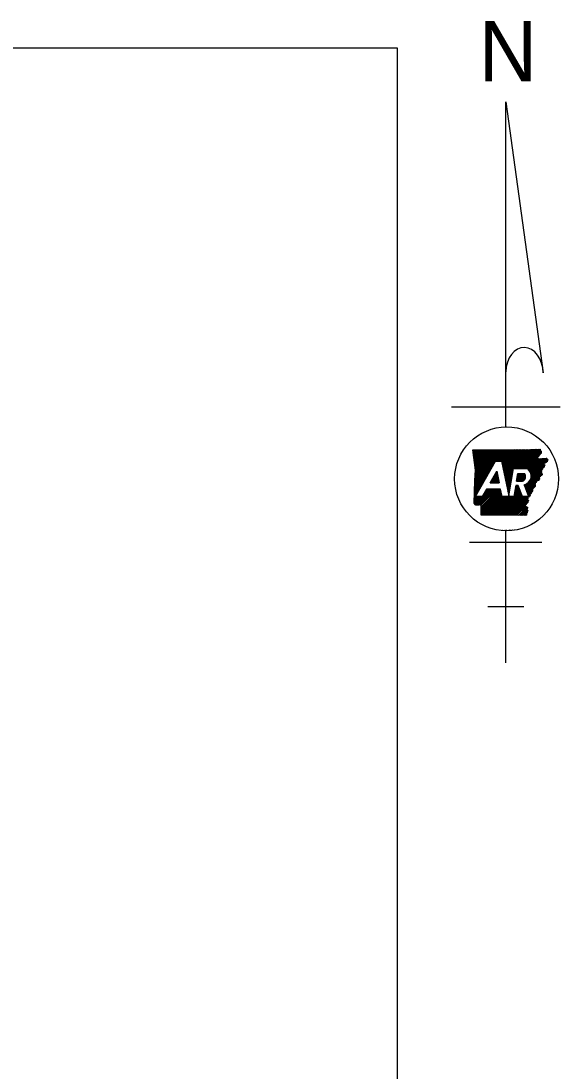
# Model space of a CAD drawing. Extents: x -984 to 3998, y 83 to 2143.
# Drawn here: x 751 to 1030, y 1535 to 2078 of the extents above; entities that cross this region are included whole.
import ezdxf

# ---------------------------------------------------------------- set-up
doc = ezdxf.new("R2010")
doc.units = 0
doc.layers.add('Level 47', color=7, linetype='Continuous')
doc.layers.add('Level 57', color=7, linetype='Continuous')

msp = doc.modelspace()

# ---------------------------------------------------------------- linework, layer by layer
at = {"layer": 'Level 47'}
for p, q in [((1002.31, 2036.19), (1021.71, 1895.95)), ((1002.31, 1868.02), (1002.31, 2036.19)), ((974.22, 1878.42), (1030.38, 1878.42)), ((985.27, 1855.97), (985.5, 1856.2)), ((985.35, 1855.31), (986.24, 1856.2)), ((985.43, 1854.65), (986.99, 1856.2)), ((985.52, 1853.99), (987.73, 1856.2)), ((985.6, 1853.33), (988.47, 1856.2)), ((985.68, 1852.67), (989.22, 1856.2)), ((985.76, 1852.01), (989.96, 1856.2)), ((985.85, 1851.35), (990.7, 1856.2)), ((985.93, 1850.68), (991.44, 1856.2)), ((986.01, 1850.02), (992.19, 1856.2)), ((986.09, 1849.36), (992.93, 1856.2)), ((986.18, 1848.7), (993.67, 1856.2)), ((986.26, 1848.04), (994.42, 1856.2)), ((986.34, 1847.38), (995.16, 1856.2)), ((986.37, 1839.97), (1002.61, 1856.21)), ((986.39, 1840.74), (1001.86, 1856.21)), ((986.42, 1841.51), (1001.12, 1856.21)), ((986.42, 1846.72), (995.9, 1856.2)), ((986.44, 1842.28), (1000.37, 1856.21)), ((986.47, 1843.05), (999.63, 1856.21)), ((986.49, 1843.82), (998.88, 1856.21)), ((986.51, 1846.06), (996.65, 1856.2)), ((986.52, 1844.58), (998.14, 1856.2)), ((986.54, 1845.35), (997.39, 1856.2)), ((997.4, 1850.27), (1003.35, 1856.21)), ((998.15, 1850.27), (1004.1, 1856.22)), ((998.89, 1850.27), (1004.85, 1856.22)), ((999.63, 1850.27), (1005.6, 1856.23)), ((1000.1, 1849.99), (1006.36, 1856.25)), ((1000.23, 1849.37), (1007.11, 1856.26)), ((1000.36, 1848.76), (1007.87, 1856.27)), ((1000.49, 1848.15), (1008.62, 1856.28)), ((1000.62, 1847.54), (1009.38, 1856.29)), ((1000.75, 1846.92), (1010.13, 1856.3)), ((1000.88, 1846.31), (1010.89, 1856.32)), ((1001.01, 1845.7), (1011.64, 1856.33)), ((1001.15, 1845.09), (1012.4, 1856.34)), ((1001.28, 1844.48), (1013.15, 1856.35)), ((1001.41, 1843.86), (1013.91, 1856.36)), ((1001.54, 1843.25), (1014.66, 1856.38)), ((1001.67, 1842.64), (1015.42, 1856.39)), ((1001.8, 1842.03), (1016.18, 1856.41)), ((1006.96, 1846.45), (1016.94, 1856.42)), ((1007.71, 1846.45), (1017.7, 1856.44)), ((1008.45, 1846.45), (1018.46, 1856.46)), ((1009.19, 1846.45), (1019.23, 1856.48)), ((1009.94, 1846.45), (1019.99, 1856.5)), ((1010.68, 1846.45), (1020.15, 1855.92)), ((1011.42, 1846.45), (1020.51, 1855.53)), ((1012.17, 1846.45), (1020.61, 1854.89)), ((986.31, 1838.43), (995.4, 1847.52)), ((986.34, 1839.2), (996.37, 1849.23)), ((986.59, 1831.95), (996.96, 1850.27)), ((996.96, 1850.27), (1000.04, 1850.27)), ((1012.91, 1846.45), (1018.91, 1852.45)), ((1013.59, 1846.38), (1018.76, 1851.56)), ((1013.99, 1846.04), (1019.55, 1851.6)), ((1014.35, 1845.66), (1020.33, 1851.64)), ((1014.68, 1845.24), (1021.11, 1851.68)), ((1014.95, 1844.77), (1021.9, 1851.72)), ((1015.18, 1844.25), (1022.68, 1851.76)), ((1015.3, 1841.4), (1022.05, 1848.15)), ((1015.35, 1843.68), (1023.39, 1851.72)), ((1015.45, 1843.04), (1023.73, 1851.32)), ((1015.46, 1842.3), (1021.96, 1848.81)), ((1021.21, 1846.57), (1022.13, 1847.49)), ((1023.41, 1850.25), (1024.08, 1850.93)), ((986.24, 1836.13), (992.49, 1842.38)), ((986.26, 1836.9), (993.46, 1844.09)), ((986.29, 1837.66), (994.43, 1845.81)), ((994.21, 1839.14), (997.61, 1845.13)), ((994.25, 1839.14), (998.07, 1842.96)), ((994.99, 1839.14), (998.2, 1842.35)), ((995.14, 1840.77), (997.94, 1843.57)), ((996.11, 1842.49), (997.81, 1844.19)), ((997.08, 1844.2), (997.68, 1844.8)), ((1001.93, 1841.41), (1006.15, 1845.63)), ((1002.06, 1840.8), (1005.99, 1844.73)), ((1002.19, 1840.19), (1005.84, 1843.83)), ((1002.32, 1839.58), (1005.68, 1842.93)), ((1002.46, 1838.96), (1005.52, 1842.03)), ((1006.29, 1846.45), (1013.49, 1846.45)), ((1007.86, 1839.95), (1011.77, 1843.86)), ((1008.01, 1840.85), (1011.03, 1843.86)), ((1008.17, 1841.75), (1010.28, 1843.86)), ((1008.32, 1842.65), (1009.54, 1843.86)), ((1008.48, 1843.55), (1008.8, 1843.86)), ((1008.54, 1843.86), (1011.92, 1843.86)), ((1008.6, 1839.95), (1012.18, 1843.53)), ((1009.35, 1839.95), (1012.43, 1843.04)), ((1010.09, 1839.95), (1012.57, 1842.43)), ((1012.23, 1836.85), (1020.47, 1845.09)), ((1012.43, 1836.3), (1020.61, 1844.48)), ((1012.63, 1835.76), (1020.75, 1843.88)), ((1012.83, 1835.22), (1020.89, 1843.27)), ((1014.65, 1840.01), (1020.33, 1845.69)), ((986.16, 1833.82), (989.58, 1837.24)), ((986.19, 1834.59), (990.55, 1838.95)), ((986.21, 1835.36), (991.52, 1840.66)), ((994.21, 1839.14), (998.89, 1839.14)), ((995.74, 1839.14), (998.33, 1841.74)), ((996.48, 1839.14), (998.46, 1841.12)), ((997.22, 1839.14), (998.59, 1840.51)), ((997.97, 1839.14), (998.73, 1839.9)), ((998.71, 1839.14), (998.86, 1839.29)), ((1002.59, 1838.35), (1005.36, 1841.13)), ((1002.72, 1837.74), (1005.21, 1840.23)), ((1002.85, 1837.13), (1005.05, 1839.33)), ((1002.98, 1836.52), (1004.89, 1838.43)), ((1003.11, 1835.9), (1004.74, 1837.53)), ((1003.24, 1835.29), (1004.58, 1836.63)), ((1006.9, 1834.49), (1009.12, 1836.71)), ((1007.06, 1835.39), (1008.92, 1837.25)), ((1007.22, 1836.29), (1008.7, 1837.78)), ((1007.37, 1837.19), (1007.96, 1837.78)), ((1008.72, 1837.78), (1007.48, 1837.78)), ((1007.85, 1839.95), (1010.94, 1839.95)), ((1010.88, 1831.95), (1008.72, 1837.78)), ((1010.83, 1839.95), (1012.51, 1841.63)), ((1011.77, 1838.09), (1014.04, 1831.95)), ((1011.83, 1837.93), (1012.06, 1838.16)), ((1012.03, 1837.39), (1013.44, 1838.8)), ((1013.03, 1834.68), (1017.49, 1839.13)), ((1013.23, 1834.13), (1017.41, 1838.31)), ((1013.43, 1833.59), (1017.32, 1837.48)), ((1018.35, 1839.99), (1019.39, 1841.03)), ((985.99, 1828.45), (989.5, 1831.95)), ((986.01, 1829.21), (988.75, 1831.95)), ((986.03, 1829.98), (988.01, 1831.95)), ((986.06, 1830.75), (987.27, 1831.95)), ((986.08, 1831.51), (986.67, 1832.1)), ((986.11, 1832.28), (987.64, 1833.81)), ((986.14, 1833.05), (988.61, 1835.52)), ((986.27, 1827.98), (994.08, 1835.8)), ((990.14, 1831.95), (986.59, 1831.95)), ((986.71, 1827.68), (994.83, 1835.8)), ((987.25, 1827.47), (995.57, 1835.8)), ((988.13, 1827.61), (996.31, 1835.8)), ((988.88, 1827.62), (997.06, 1835.8)), ((989.47, 1827.46), (997.8, 1835.8)), ((989.49, 1826), (999.29, 1835.8)), ((989.49, 1826.74), (998.54, 1835.8)), ((989.5, 1825.26), (999.68, 1835.44)), ((989.5, 1824.52), (999.81, 1834.83)), ((989.5, 1823.78), (999.94, 1834.22)), ((989.5, 1823.04), (1000.07, 1833.61)), ((989.51, 1822.31), (1000.2, 1833)), ((992.32, 1835.8), (990.14, 1831.95)), ((990.26, 1822.31), (1000.33, 1832.38)), ((990.99, 1833.44), (993.34, 1835.8)), ((991, 1822.3), (1000.65, 1831.95)), ((991.74, 1822.3), (1001.39, 1831.95)), ((991.96, 1835.16), (992.6, 1835.8)), ((999.6, 1835.8), (992.32, 1835.8)), ((992.48, 1822.3), (1002.13, 1831.95)), ((993.22, 1822.3), (1002.88, 1831.95)), ((993.97, 1822.3), (1003.62, 1831.95)), ((994.71, 1822.3), (1004.36, 1831.95)), ((995.45, 1822.3), (1005.11, 1831.95)), ((996.19, 1822.3), (1005.85, 1831.95)), ((996.94, 1822.29), (1009.72, 1835.08)), ((997.68, 1822.29), (1009.92, 1834.54)), ((998.42, 1822.29), (1010.12, 1833.99)), ((999.16, 1822.29), (1010.32, 1833.45)), ((999.9, 1822.29), (1010.52, 1832.91)), ((1006.46, 1831.95), (1000.43, 1831.95)), ((1000.65, 1822.29), (1010.72, 1832.37)), ((1001.39, 1822.29), (1011.05, 1831.95)), ((1002.13, 1822.29), (1011.8, 1831.95)), ((1002.87, 1822.28), (1012.54, 1831.95)), ((1003.37, 1834.68), (1004.42, 1835.73)), ((1003.5, 1834.07), (1004.27, 1834.83)), ((1003.61, 1822.28), (1013.28, 1831.95)), ((1003.63, 1833.45), (1004.11, 1833.93)), ((1003.77, 1832.84), (1003.95, 1833.03)), ((1004.36, 1822.28), (1013.53, 1831.46)), ((1006.59, 1832.69), (1009.52, 1835.62)), ((1006.75, 1833.59), (1009.32, 1836.16)), ((1014.04, 1831.95), (1010.88, 1831.95)), ((1013.63, 1833.05), (1015.91, 1835.33)), ((1013.83, 1832.5), (1015.6, 1834.26)), ((1005.1, 1822.28), (1013.57, 1830.75)), ((1005.84, 1822.28), (1013.6, 1830.04)), ((1006.58, 1822.28), (1013.63, 1829.33)), ((1007.32, 1822.28), (1012.41, 1827.36)), ((1008.07, 1822.28), (1012.64, 1826.85)), ((1008.81, 1822.27), (1012.87, 1826.34)), ((1009.55, 1822.27), (1013.1, 1825.82)), ((1010.29, 1822.27), (1013.33, 1825.31)), ((1011.04, 1822.27), (1013.52, 1824.76)), ((1011.78, 1822.27), (1013.19, 1823.68)), ((1012.52, 1822.27), (1012.85, 1822.6)), ((1002.31, 1745.97), (1002.31, 1814.22)), ((983.59, 1808.42), (1021.03, 1808.42)), ((992.94, 1775.17), (1011.67, 1775.17))]:
    msp.add_line(p, q, dxfattribs=at)
for points in [[(985.24, 1856.2), (995.49, 1856.2), (1004.5, 1856.22), (1015.11, 1856.38), (1020.03, 1856.5)], [(985.24, 1856.2), (995.5, 1856.2), (1004.5, 1856.22), (1015.11, 1856.38), (1020.03, 1856.5)], [(986.37, 1840.26), (986.55, 1845.66), (985.24, 1856.2)], [(985.98, 1828.46), (986.55, 1845.66), (985.24, 1856.2)], [(1000.04, 1850.27), (1003.85, 1832.44), (1006.29, 1846.45)], [(1023.26, 1851.78), (1024.14, 1850.86), (1021.93, 1849.04), (1022.17, 1847.2), (1020.27, 1845.95), (1020.92, 1843.13), (1019.46, 1841.79), (1019.33, 1840.34), (1017.55, 1839.7), (1017.27, 1836.97), (1016, 1835.6), (1015.38, 1833.54), (1013.52, 1831.83), (1013.66, 1828.83), (1012.39, 1827.41), (1013.54, 1824.83), (1012.75, 1822.27)], [(1018.51, 1851.55), (1023.32, 1851.79)], [(1018.51, 1851.54), (1023.33, 1851.79)], [(997.61, 1845.13), (998.89, 1839.14)], [(1007.85, 1839.95), (1008.54, 1843.86)], [(985.99, 1828.46), (986.37, 1840.26)], [(1007.48, 1837.78), (1006.46, 1831.95)], [(1000.43, 1831.95), (999.6, 1835.8)], [(1012.75, 1822.27), (989.5, 1822.31), (989.49, 1827.44)], [(1012.75, 1822.27), (989.5, 1822.31), (989.49, 1827.44)]]:
    msp.add_lwpolyline(points, dxfattribs=at)
for centre, major_axis, ratio, start_param, end_param in [((1012, 1895.65), (-0.41, 13.48), 0.719778, 4.712385, 7.768526), ((1010.2, 1842.21), (-2.38, 0), 0.999987, 1.887169, 3.90762), ((1010.82, 1842.64), (-4.65, 0), 0.999987, 1.777838, 4.099264)]:
    msp.add_ellipse(centre, major_axis=major_axis, ratio=ratio, start_param=start_param, end_param=end_param, dxfattribs=at)
msp.add_ellipse((1002.74, 1841.12), major_axis=(26.9, 0), ratio=0.999976, dxfattribs=at)
for points in [[(1020.03, 1856.5), (1020.07, 1856.22), (1020.15, 1856.07), (1020.16, 1855.8), (1020.27, 1855.69), (1020.46, 1855.58), (1020.62, 1855.39), (1020.66, 1855.18), (1020.61, 1854.96), (1020.6, 1854.7), (1020.57, 1854.49), (1020.53, 1854.3), (1020.38, 1854.14), (1020.24, 1854.02), (1020.1, 1853.89), (1020.01, 1853.75), (1019.85, 1853.6), (1019.68, 1853.44), (1019.54, 1853.3), (1019.41, 1853.12), (1019.35, 1852.93), (1019.2, 1852.79), (1019.09, 1852.66), (1018.94, 1852.49), (1018.86, 1852.32), (1018.72, 1852.12), (1018.68, 1851.93), (1018.59, 1851.78), (1018.58, 1851.75)], [(1020.03, 1856.5), (1020.07, 1856.22), (1020.15, 1856.07), (1020.17, 1855.81), (1020.27, 1855.69), (1020.46, 1855.58), (1020.62, 1855.39), (1020.66, 1855.18), (1020.61, 1854.96), (1020.6, 1854.71), (1020.57, 1854.49), (1020.54, 1854.3), (1020.38, 1854.14), (1020.24, 1854.02), (1020.1, 1853.89), (1020.01, 1853.75), (1019.84, 1853.6), (1019.68, 1853.44), (1019.55, 1853.3), (1019.41, 1853.12), (1019.35, 1852.93), (1019.2, 1852.79), (1019.09, 1852.66), (1018.94, 1852.49), (1018.86, 1852.32), (1018.71, 1852.12), (1018.68, 1851.93), (1018.59, 1851.78), (1018.58, 1851.75)], [(1023.26, 1851.79), (1023.32, 1851.79), (1023.54, 1851.56), (1023.63, 1851.37), (1023.78, 1851.27), (1023.94, 1851.21), (1024.06, 1851.06), (1024.14, 1850.9), (1024.09, 1850.76), (1023.91, 1850.75), (1023.72, 1850.72), (1023.53, 1850.73), (1023.37, 1850.59), (1023.52, 1850.43), (1023.7, 1850.27), (1023.75, 1850.1), (1023.65, 1849.93), (1023.44, 1849.84), (1023.25, 1849.76), (1023.07, 1849.62), (1022.99, 1849.47), (1022.79, 1849.41), (1022.59, 1849.35), (1022.41, 1849.33), (1022.21, 1849.29), (1022.01, 1849.19), (1021.93, 1849.03), (1021.96, 1848.8), (1021.95, 1848.55), (1022.16, 1848.47), (1022.34, 1848.46), (1022.52, 1848.37), (1022.5, 1848.23), (1022.37, 1848.05), (1022.21, 1847.91), (1022.05, 1847.84), (1021.9, 1847.7), (1021.96, 1847.57), (1022.09, 1847.49), (1022.18, 1847.34), (1022.17, 1847.21), (1022.02, 1847.11), (1021.85, 1847.15), (1021.73, 1847.31), (1021.59, 1847.36), (1021.47, 1847.41), (1021.33, 1847.33), (1021.33, 1847.15), (1021.28, 1846.95), (1021.33, 1846.81), (1021.38, 1846.6), (1021.38, 1846.45), (1021.33, 1846.23), (1021.22, 1846.01), (1021.1, 1845.94), (1021.04, 1846.18), (1021.02, 1846.38), (1020.94, 1846.5), (1020.84, 1846.5), (1020.7, 1846.41), (1020.56, 1846.26), (1020.38, 1846.1), (1020.27, 1845.94), (1020.33, 1845.75), (1020.46, 1845.7), (1020.57, 1845.73), (1020.63, 1845.86), (1020.73, 1845.88), (1020.84, 1845.68)], [(1020.84, 1845.68), (1020.87, 1845.5), (1020.76, 1845.31), (1020.72, 1845.11), (1020.73, 1844.91), (1020.53, 1844.8), (1020.36, 1844.67), (1020.46, 1844.52), (1020.65, 1844.38), (1020.84, 1844.28), (1020.96, 1844.17), (1020.99, 1843.91), (1021.02, 1843.74), (1021.09, 1843.51), (1021.11, 1843.36), (1021, 1843.17), (1020.87, 1843.13), (1020.72, 1843.17), (1020.56, 1843.18), (1020.43, 1843.06), (1020.33, 1842.88), (1020.24, 1842.7), (1020.16, 1842.55), (1020.09, 1842.39), (1019.96, 1842.19), (1019.79, 1842.16), (1019.58, 1842.11), (1019.46, 1841.97), (1019.48, 1841.74), (1019.6, 1841.58), (1019.68, 1841.39), (1019.75, 1841.21), (1019.72, 1841), (1019.63, 1840.84), (1019.52, 1840.74), (1019.46, 1840.54), (1019.38, 1840.39), (1019.3, 1840.33), (1019.15, 1840.35), (1018.99, 1840.38), (1018.85, 1840.37), (1018.72, 1840.3), (1018.58, 1840.34), (1018.44, 1840.5), (1018.33, 1840.61), (1018.2, 1840.65), (1018.07, 1840.58), (1018.05, 1840.37), (1018.11, 1840.16), (1018.16, 1839.87), (1018.11, 1839.69), (1018.09, 1839.4)], [(1018.09, 1839.4), (1017.87, 1839.23), (1017.76, 1839.05), (1017.2, 1839.1), (1017.22, 1838.91), (1017.02, 1838.8), (1016.84, 1838.67), (1016.94, 1838.52), (1017.13, 1838.38), (1017.32, 1838.27), (1017.44, 1838.17), (1017.47, 1837.9), (1017.51, 1837.74), (1017.57, 1837.51), (1017.59, 1837.35), (1017.48, 1837.17), (1017.34, 1837.13), (1017.21, 1837.17), (1017.04, 1837.18), (1016.91, 1837.06), (1016.81, 1836.88), (1016.72, 1836.7), (1016.65, 1836.55), (1016.57, 1836.38), (1016.44, 1836.19), (1016.27, 1836.16), (1016.07, 1836.11), (1015.94, 1835.97), (1015.96, 1835.74), (1016.08, 1835.58), (1016.17, 1835.38), (1016.23, 1835.21), (1016.2, 1835), (1016.11, 1834.83), (1016, 1834.74), (1015.94, 1834.54), (1015.86, 1834.38), (1015.79, 1834.34), (1015.64, 1834.35), (1015.47, 1834.38), (1015.33, 1834.37), (1015.2, 1834.3), (1015.06, 1834.34), (1014.92, 1834.49), (1014.81, 1834.61), (1014.68, 1834.65), (1014.55, 1834.58), (1014.53, 1834.37), (1014.59, 1834.16), (1014.65, 1833.87), (1014.59, 1833.69), (1014.57, 1833.39)], [(1014.57, 1833.39), (1014.55, 1833.39), (1014.44, 1833.24), (1014.5, 1833.02), (1014.75, 1832.93), (1014.86, 1832.72), (1014.87, 1832.53), (1014.79, 1832.27), (1014.67, 1832.14), (1014.45, 1832.09), (1014.28, 1832.06), (1014.26, 1831.77), (1014.18, 1831.62), (1014.05, 1831.58), (1013.86, 1831.67), (1013.74, 1831.72), (1013.6, 1831.78), (1013.43, 1831.89), (1013.29, 1831.87), (1013.33, 1831.59), (1013.34, 1831.58), (1013.5, 1831.37), (1013.64, 1831.2), (1013.71, 1831.01)], [(1014.57, 1833.39), (1014.55, 1833.39), (1014.44, 1833.24), (1014.5, 1833.02), (1014.75, 1832.93), (1014.86, 1832.72), (1014.87, 1832.53), (1014.79, 1832.27), (1014.67, 1832.14), (1014.45, 1832.09), (1014.28, 1832.06), (1014.26, 1831.77), (1014.18, 1831.62), (1014.05, 1831.58), (1013.86, 1831.67), (1013.74, 1831.72), (1013.6, 1831.78), (1013.43, 1831.89), (1013.29, 1831.87), (1013.33, 1831.59), (1013.34, 1831.58), (1013.5, 1831.37), (1013.64, 1831.2), (1013.71, 1831.01)], [(989.49, 1827.44), (989.52, 1827.42), (989.4, 1827.51), (989.23, 1827.59), (989.05, 1827.6), (988.81, 1827.63), (988.62, 1827.65), (988.41, 1827.79), (988.2, 1827.65), (987.96, 1827.55), (987.82, 1827.66), (987.63, 1827.58), (987.51, 1827.62), (987.28, 1827.47), (987.07, 1827.53), (986.92, 1827.48), (986.73, 1827.49), (986.69, 1827.7), (986.51, 1827.74), (986.35, 1827.82), (986.24, 1828.05), (986.17, 1828.22), (985.98, 1828.46)], [(989.49, 1827.44), (989.52, 1827.43), (989.4, 1827.51), (989.23, 1827.59), (989.04, 1827.6), (988.81, 1827.63), (988.61, 1827.65), (988.41, 1827.79), (988.2, 1827.65), (987.96, 1827.54), (987.82, 1827.66), (987.63, 1827.58), (987.5, 1827.62), (987.28, 1827.47), (987.07, 1827.53), (986.92, 1827.48), (986.73, 1827.49), (986.69, 1827.7), (986.51, 1827.73), (986.35, 1827.82), (986.24, 1828.04), (986.17, 1828.22), (985.99, 1828.46)], [(1013.71, 1831.01), (1013.65, 1830.86), (1013.58, 1830.61), (1013.6, 1830.39), (1013.7, 1830.21), (1013.85, 1830.11), (1014.02, 1829.96), (1014, 1829.74), (1013.91, 1829.66), (1013.68, 1829.71), (1013.51, 1829.79), (1013.37, 1829.75), (1013.17, 1829.65), (1013.03, 1829.63), (1013.03, 1829.33), (1013.23, 1829.11), (1013.4, 1829.11), (1013.6, 1829.09), (1013.67, 1828.86), (1013.55, 1828.67), (1013.36, 1828.57), (1013.12, 1828.69), (1012.95, 1828.81), (1012.78, 1828.92), (1012.56, 1828.98), (1012.44, 1828.95), (1012.38, 1828.69), (1012.49, 1828.45), (1012.65, 1828.28), (1012.8, 1828.07), (1012.78, 1827.9), (1012.66, 1827.86), (1012.46, 1827.82), (1012.34, 1827.76), (1012.31, 1827.7), (1012.37, 1827.49), (1012.43, 1827.26), (1012.43, 1827.07), (1012.36, 1826.91), (1012.25, 1826.66), (1012.26, 1826.5), (1012.34, 1826.42), (1012.44, 1826.44), (1012.56, 1826.53), (1012.65, 1826.63), (1012.72, 1826.76), (1012.85, 1826.87), (1013.01, 1826.77), (1013.05, 1826.57), (1012.96, 1826.41), (1012.82, 1826.33), (1012.66, 1826.26), (1012.54, 1826.13), (1012.57, 1825.96), (1012.66, 1825.87), (1012.9, 1825.92), (1013.06, 1825.99), (1013.15, 1826.07), (1013.25, 1826.18), (1013.31, 1826.29), (1013.39, 1826.41), (1013.54, 1826.44), (1013.61, 1826.34), (1013.58, 1826.13), (1013.5, 1825.92), (1013.37, 1825.75), (1013.24, 1825.63), (1013.08, 1825.37), (1013.11, 1825.13), (1013.17, 1824.93), (1013.26, 1824.78), (1013.41, 1824.81), (1013.58, 1824.83), (1013.68, 1824.75), (1013.67, 1824.57), (1013.55, 1824.4), (1013.43, 1824.23), (1013.36, 1824.01), (1013.39, 1823.85), (1013.39, 1823.71), (1013.34, 1823.54), (1013.25, 1823.45), (1013.01, 1823.46), (1012.77, 1823.48), (1012.63, 1823.41), (1012.66, 1823.2), (1012.8, 1823.04), (1012.9, 1822.95), (1013.05, 1822.78), (1013.11, 1822.63), (1013.1, 1822.5), (1013, 1822.39), (1012.75, 1822.27)], [(1013.71, 1831.01), (1013.65, 1830.86), (1013.58, 1830.61), (1013.6, 1830.39), (1013.7, 1830.21), (1013.85, 1830.11), (1014.02, 1829.96), (1014, 1829.74), (1013.91, 1829.66), (1013.68, 1829.71), (1013.51, 1829.79), (1013.37, 1829.75), (1013.17, 1829.65), (1013.03, 1829.63), (1013.03, 1829.33), (1013.23, 1829.11), (1013.4, 1829.11), (1013.6, 1829.09), (1013.67, 1828.86), (1013.55, 1828.67), (1013.36, 1828.57), (1013.12, 1828.69), (1012.95, 1828.81), (1012.78, 1828.92), (1012.56, 1828.98), (1012.44, 1828.95), (1012.38, 1828.69), (1012.49, 1828.45), (1012.65, 1828.28), (1012.8, 1828.07), (1012.78, 1827.9), (1012.66, 1827.86), (1012.46, 1827.82), (1012.34, 1827.76), (1012.31, 1827.7), (1012.37, 1827.49), (1012.43, 1827.26), (1012.43, 1827.07), (1012.36, 1826.91), (1012.25, 1826.66), (1012.26, 1826.5), (1012.34, 1826.42), (1012.44, 1826.44), (1012.56, 1826.53), (1012.65, 1826.63), (1012.72, 1826.76), (1012.85, 1826.87), (1013.01, 1826.77), (1013.05, 1826.57), (1012.96, 1826.41), (1012.82, 1826.33), (1012.66, 1826.26), (1012.54, 1826.13), (1012.57, 1825.96), (1012.66, 1825.87), (1012.9, 1825.92), (1013.06, 1825.99), (1013.15, 1826.07), (1013.25, 1826.18), (1013.31, 1826.29), (1013.39, 1826.41), (1013.54, 1826.44), (1013.61, 1826.34), (1013.58, 1826.13), (1013.5, 1825.92), (1013.37, 1825.75), (1013.24, 1825.63), (1013.08, 1825.37), (1013.11, 1825.13), (1013.17, 1824.93), (1013.26, 1824.78), (1013.41, 1824.81), (1013.58, 1824.83), (1013.68, 1824.75), (1013.67, 1824.57), (1013.55, 1824.4), (1013.43, 1824.23), (1013.36, 1824.01), (1013.39, 1823.85), (1013.39, 1823.71), (1013.34, 1823.54), (1013.25, 1823.45), (1013.01, 1823.46), (1012.77, 1823.48), (1012.63, 1823.41), (1012.66, 1823.2), (1012.8, 1823.04), (1012.9, 1822.95), (1013.05, 1822.78), (1013.11, 1822.63), (1013.1, 1822.5), (1013, 1822.39), (1012.75, 1822.27)]]:
    msp.add_spline(points, degree=3, dxfattribs=at)
at = {"layer": 'Level 57'}
msp.add_lwpolyline([(215, 2064.18), (946.14, 2064.18), (946.14, 1419.54), (215, 1419.54)], close=True, dxfattribs=at)

# ---------------------------------------------------------------- texts
at = {"layer": 'Level 47'}
for s, height, p in [('N', 31.3, (988.35, 2046.77)), ('STS 10-03-17', 0.7778, (1000.17, 1814.44))]:
    msp.add_text(s, height=height, dxfattribs=at).set_placement(p)

doc.saveas('drawing.dxf')
